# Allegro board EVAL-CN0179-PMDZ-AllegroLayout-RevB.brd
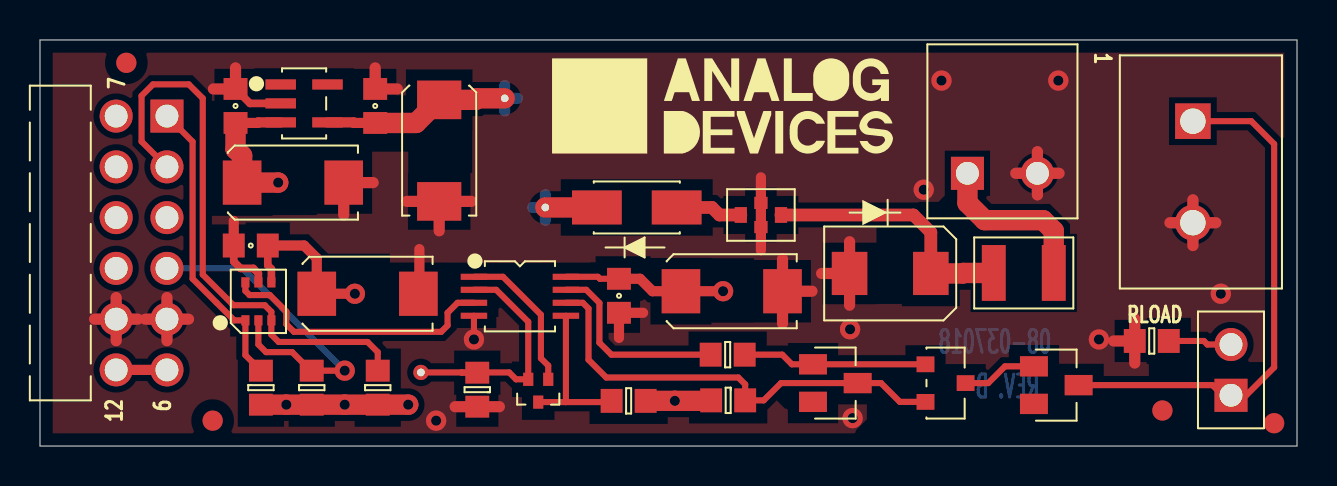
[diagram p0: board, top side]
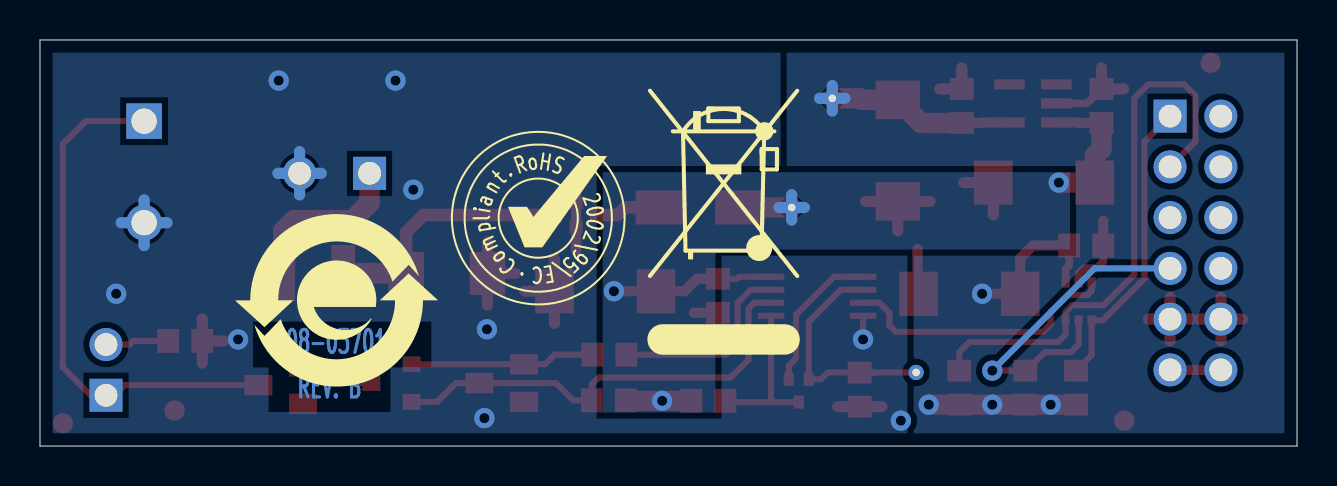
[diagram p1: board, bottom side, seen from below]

Outline 62.87 x 20.32 mm; copper layers: TOP, BOTTOM. Coordinates in mm from the lower left corner of the outline.
Outline path: 0,20.32 0,0 62.87,0 62.87,20.32 0,20.32

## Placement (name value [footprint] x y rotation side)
A1  AD8657ARMZ  [MSOP8]  24 7.49 270 top
C2  0.1uF  [C0805-4P]  36.05 11.56 180 top
C3  10uf  [C2312]  12.65 13.18 0 top
C4  0.1UF  [C0603]  9.78 17.02 270 top
C5  0.1UF  [C0603]  10.54 10.03 0 top
C6  10uf  [C2312]  16.38 7.62 0 top
C7  0.1UF  [C0603]  16.76 17.02 270 top
C8  10uf  [C2312]  19.96 14.78 270 top
C9  0.1UF  [C0603]  28.96 7.52 90 top
C10  10uf  [C2312]  34.59 7.75 0 top
CR1  SMBJ5357B-TP  [DO214AA3]  42.52 8.64 180 top
D1  SBR1A40SA-13  [SMA-2]  29.84 11.94 0 top
D2  BZX84C18LT1G  [SOT23]  39.78 3.15 270 top
F1  0.05A  [F1210_A]  49.2 8.66 180 top
I_OUT  OSTTC022162  [CNHDR1X2H406]  57.66 16.26 270 top
J1  M20-9990246  [CNHARWIN-M20-9990246]  59.56 2.54 90 top
NOREF  -  []  0 0 0 top
NOREF#2  -  []  26.16 50.97 0 top
NOREF#3  -  []  -219.71 -146.05 0 top
NOREF#4  -  []  -81.94 303.06 0 top
NOREF#5  -  []  34.16 17.02 0 top
NOREF#6  -  []  49.53 40.64 180 top
NOREF#7  -  []  -219.71 -146.05 0 top
NOREF#8  -  []  62.87 20.32 0 top
NOREF#9  -  [unnamed#2]  61.72 1.14 0 top
NOREF#10  -  [unnamed#2]  8.64 1.27 0 top
NOREF#11  -  []  6.35 16.51 0 top
NOREF#12  -  []  0 0 0 top
NOREF#13  -  []  0 0 0 top
NOREF#14  -  []  62.87 0 90 top
NOREF#15  -  []  153.85 303.38 0 top
NOREF#16  -  []  -219.71 -146.05 0 top
NOREF#17  -  []  49.53 0 90 top
NOREF#18  -  [unnamed#2]  4.32 19.18 0 top
NOREF#19  -  []  62.87 20.32 0 top
NOREF#20  -  []  2.54 40.64 270 top
NOREF#21  -  []  6.35 16.51 0 top
NOREF#22  -  [unnamed#2]  56.13 1.78 0 top
NOREF#23  -  []  2.54 0 0 top
NOREF#24  -  []  161.54 52.07 0 top
NOREF#25  -  []  19.41 21.46 180 bottom
NOREF#26  -  []  37.95 11.4 180 bottom
NOREF#27  -  []  48.03 7.29 180 bottom
P1  ED550/2DS  [CNOSTED550-2DS]  46.38 13.65 0 top
P2  TSW-106-25-F-D-RA  [CNHDRRA2X6H240]  6.35 16.51 270 top
Q1  2N7002T  [SOT523F]  24.92 2.77 180 top
Q2  SI2319DS-T1-E3  [SOT23-M3]  45.29 3.15 270 top
R1  10K  [R0603]  11.05 2.92 270 top
R2  10K  [R0603]  13.59 2.92 270 top
R3  10K  [R0603]  16.89 2.92 270 top
R4  1K  [R0603]  29.44 2.26 0 top
R5  2.49K  [R0603]  21.87 2.82 90 top
R6  100  [R0603]  34.39 4.57 0 top
R7  100  [R0603]  34.42 2.29 180 top
R8  250  [R0603]  55.6 5.26 0 top
U1  AD5641BKSZ  [SC70-6]  10.92 7.24 0 top
U2  ADR02BUJZ  [TSOT-5]  13.21 17.14 270 top
U3  BAS21LT1G  [SOT23]  50.83 3.05 270 top
UNK5V  TESTPAD  [TPC30D15]  23.24 17.4 0 top
V_RS  TESTPAD  [TPC30D15]  19.05 3.68 0 top
V_SY  TESTPAD  [TPC30D15]  25.27 11.94 0 top

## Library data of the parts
A1 = AD8657_V3: User Part Number: UPN; part number: AD8657_V3_SM-AD8657ARMZ,E019579,MSOP8,N/A
C2 = CAP4P_V3: Tolerance: -20+50; User Part Number: UPN; part number: CAP4P_V3_SM-0.1UF,25V,-20+50,E018137,C0805-4P; tolerance: -20+50
C3 C6 C8 C10 = CAPP: Tolerance: 10; User Part Number: UPN; part number: CAPP_SM-10UF,25V,10,E014558,C2312; tolerance: 10
C4 C5 C7 C9 = CAP: Tolerance: 10; User Part Number: UPN; alternate symbols: (C0402H22_ALT,C0201-2,C0402_A,C0402_ALT); part number: CAP_SM-0.1UF,25V,10,E007204,C0603; tolerance: 10
CR1 = DIOZNR: User Part Number: UPN; Tolerance: 5; part number: DIOZNR_SM-SMBJ5357B-TP,20V,5,E019629,DO214AA3; tolerance: 5
D1 = DIO: User Part Number: UPN; Tolerance: N/A; alternate symbols: (DO15_ALT); part number: DIO_SM-SBR1A40SA-13,40V,N/A,E015547,SMA-2; tolerance: N/A
D2 = DIOZNR3P_V3: User Part Number: UPN; Tolerance: 6; part number: DIOZNR3P_V3_SM-BZX84C18LT1G,18V,6,E019209,SOT23; tolerance: 6
F1 = FSFUSE: User Part Number: UPN; part number: FSFUSE_SM-0.05A,60V,E017159,F1210_A
I_OUT = CN2P: User Part Number: UPN; part number: CN2P_TH-OSTTC022162,E016936,CNHDR1X2H406
J1 = CN2P: User Part Number: UPN; part number: CN2P_TH-M20-9990246,E010843,CNHARWIN-M20-9990246
P1 = CN2P: User Part Number: UPN; part number: CN2P_TH-ED550/2DS,E019727,CNOSTED550-2DS
P2 = CN12P_V3: User Part Number: UPN; part number: CN12P_V3_TH-TSW-106-25-F-D-RA,E018495,CNHDRRA2X6H240
Q1 = TRAN2N7002: User Part Number: UPN; part number: TRAN2N7002_SM-2N7002T,E013674,SOT523F
Q2 = TRANSI2301DS: User Part Number: UPN; part number: TRANSI2301DS_SM-SI2319DS-T1-E3,E017810,SOT23-M3
R1-R3 = RES: Tolerance: 1; User Part Number: UPN; alternate symbols: (RRAD984L1500W75H520LD32;TO220H590_ALT;R0402_A;R0603_A); part number: RES_SM-10K,1/10W,1,E003671,R0603; tolerance: 1
R4 = RES: Tolerance: 0.1; User Part Number: UPN; alternate symbols: (RRAD984L1500W75H520LD32;TO220H590_ALT;R0402_A;R0603_A); part number: RES_SM-1K,1/10W,0.1,E003953,R0603; tolerance: 0.1
R5 = RES: Tolerance: 0.1; User Part Number: UPN; alternate symbols: (RRAD984L1500W75H520LD32;TO220H590_ALT;R0402_A;R0603_A); part number: RES_SM-2.49K,1/10W,0.1,E010318,R0603; tolerance: 0.1
R6 = RES: Tolerance: 1; User Part Number: UPN; alternate symbols: (RRAD984L1500W75H520LD32;TO220H590_ALT;R0402_A;R0603_A); part number: RES_SM-100,1/10W,1,E003668,R0603; tolerance: 1
R7 = RES: Tolerance: 0.1; User Part Number: UPN; alternate symbols: (RRAD984L1500W75H520LD32;TO220H590_ALT;R0402_A;R0603_A); part number: RES_SM-100,1/10W,0.1,E003963,R0603; tolerance: 0.1
R8 = RES: Tolerance: 0.05; User Part Number: UPN; alternate symbols: (RRAD984L1500W75H520LD32;TO220H590_ALT;R0402_A;R0603_A); part number: RES_SM-250,0.15W,0.05,E019192,R0603; tolerance: 0.05
U1 = AD56X1: User Part Number: UPN; part number: AD56X1_SM-AD5641BKSZ,E019530,SC70-6,N/A
U2 = ADR0X: User Part Number: UPN; part number: ADR0X_SM-ADR02BUJZ,E016933,TSOT-5,N/A
U3 = DIO3P_V2: User Part Number: UPN; Tolerance: N/A; part number: DIO3P_V2_SM-BAS21LT1G,250V,N/A,E019208,SOT23; tolerance: N/A
UNK5V V_RS V_SY = NCTESTPAD: User Part Number: UPN; part number: NCTESTPAD_TH-TESTPAD,E013464,TPC30D15

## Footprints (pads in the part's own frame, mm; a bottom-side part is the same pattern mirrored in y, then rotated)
C0603
  rect 1.092x1.194 smd: 1(-0.851,0) 2(0.851,0)
C0805-4P
  rect 0.61x0.787 smd: 1(-1.005,0) 3(1.005,0)
  rect 0.66x0.61 smd: G1(0,-0.605) G2(0,0.605)
C2312
  rect 1.93x2.21 smd: N(2.54,0) P(-2.54,0)
CNHARWIN-M20-9990246
  rect 1.651x1.651 hole 1.143: 1(0,0)
  round 1.651 hole 1.143: 2(2.54,0)
CNHDR1X2H406
  rect 1.778x1.778 hole 1.27: 1(0,0)
  round 1.778 hole 1.27: 2(5.08,0)
CNHDRRA2X6H240
  rect 1.651x1.651 hole 1.143: 1(0,0)
  round 1.651 hole 1.143: 2(2.54,0) 3(5.08,0) 4(7.62,0) 5(10.16,0) 6(12.7,0) 7(0,-2.54) 8(2.54,-2.54) 9(5.08,-2.54) 10(7.62,-2.54) 11(10.16,-2.54) 12(12.7,-2.54)
CNOSTED550-2DS
  rect 1.651x1.651 hole 1.143: 1(0,0)
  round 1.651 hole 1.143: 2(3.5,0)
DO214AA3
  rect 1.778x2.159 smd: A(2.032,0) C(-2.032,0)
F1210_A
  rect 1.194x2.794 smd: 1(-1.5,0) 2(1.5,0)
MSOP8
  rect 0.305x1.321 smd: 1(-0.975,-2.3) 2(-0.325,-2.3) 3(0.325,-2.3) 4(0.975,-2.3) 5(0.975,2.3) 6(0.325,2.3) 7(-0.325,2.3) 8(-0.975,2.3)
R0603
  rect 1.092x1.194 smd: 1(-0.851,0) 2(0.851,0)
SC70-6
  rect 0.406x0.508 smd: 1(-0.65,-0.95) 2(0,-0.95) 3(0.65,-0.95) 4(0.65,0.95) 5(0,0.95) 6(-0.65,0.95)
SMA-2
  rect 2.489x1.702 smd: A(1.995,0) C(-1.995,0)
SOT23
  rect 1.016x1.397 smd: 1(-0.94,-1.118) 2(0.94,-1.118) 3(0,1.118)
SOT23-M3
  rect 0.787x0.889 smd: 1(-0.94,-1.003) 2(0.94,-1.003) 3(0,1.003)
SOT523F
  rect 0.508x0.66 smd: 1(-0.5,-0.57) 2(0.5,-0.57) 3(0,0.57)
TPC30D15
  round 0.762 hole 0.381: 1(0,0)
TSOT-5
  rect 0.508x1.524 smd: 1(-0.95,-1.17) 2(0,-1.17) 3(0.95,-1.17) 4(0.95,1.17) 5(-0.95,1.17)
unnamed#2
  round 1.016 smd: (0,0)

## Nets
+5V: C5.2(N2) C6.P(N1) C7.2(N2) C8.P(N1) R1.2(N2) R2.2(N2) R3.2(N2) U1.4(VDD) U2.4(VOUT) UNK5V.1
AGND: A1.4(V-) C2.G1(GND1) C2.G2(GND2) C3.N(N2) C4.1(N1) C5.1(N1) C6.N(N2) C7.1(N1) C8.N(N2) C9.1(N1) C10.N(N2) CR1.A(P) I_OUT.2(N2) P1.2(N2) P2.5(GND1) P2.11(GND2) R5.1(N1) R8.1(N1) U1.5(GND) U2.2(GND)
+VSY: A1.8(V+) C3.P(N1) C4.2(N2) C9.2(N2) C10.P(N1) D1.C(N) R4.2(N2) R7.2(N2) U2.3(VIN) V_SY.1(N1)
DIN: P2.2(P2) R3.1(N1) U1.3(SDIN)
SCLK: P2.4(P4) R2.1(N1) U1.2(SCLK)
SYNC_N: P2.1(P1) R1.1(N1) U1.1(SYNC_N)
UNNAMED_7_AD56X1_I2_VOUT: A1.3(+IN) U1.6(VOUT)
UNNAMED_7_AD8657V3_I55_: A1.5(+IN) Q1.3(D) R4.1(N1)
UNNAMED_7_AD8657V3_I55_OUT: A1.7(OUT) R6.1(N1)
UNNAMED_7_AD8657V3_I56_OUT: A1.1(OUT) Q1.1(G)
UNNAMED_7_CN2P_I16_N1: I_OUT.1(N1) J1.1(N1) U3.3(C)
UNNAMED_7_CN2P_I53_N2: J1.2(N2) R8.2(N2)
UNNAMED_7_CN12PV3_I32_VCC1: P2.6(VCC1) P2.12(VCC2)
UNNAMED_7_DIO3PV2_I4_A: Q2.3(D) U3.1(A)
UNNAMED_7_DIOZNR3PV3_I3_N: A1.6(-IN) D2.3(N) Q2.2(S) R7.1(N1)
UNNAMED_7_DIOZNR3PV3_I3_P: D2.1(P) Q2.1(G) R6.2(N2)
UNNAMED_7_RES_I5_N2: A1.2(-IN) Q1.2(S) R5.2(N2) V_RS.1(N1)
UNNAMED_8_CAP4PV3_I22_IN: C2.1(IN) CR1.C(N) F1.2(N2)
UNNAMED_8_CAP4PV3_I22_OUT: C2.3(OUT) D1.A(P)
UNNAMED_8_CN2P_I18_N1: F1.1(N1) P1.1(N1)

Pads without a net: D2 2; P2 3 7 8 9 10; U2 1 5; U3 2

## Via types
v1: diameter 1.016, hole 0.508, TOP to BOTTOM, 17 vias

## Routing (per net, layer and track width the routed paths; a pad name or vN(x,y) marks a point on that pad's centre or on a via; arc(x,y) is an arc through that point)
+5V: length 27.6
  TOP w0.381: C5.2 11.39,9.04 11.57,8.86 U1.4
  TOP w0.508: C5.2 13.21,10.03 13.84,9.4 C6.P v1(15.75,7.62) ; U2.4 15.68,16.2 15.71,16.17 C7.2
  TOP w1.016: v1(18.41,2.07) R3.2 v1(15.24,2.07) R2.2 v1(12.32,2.07) R1.2 ; UNK5V.1 21.86,17.4 21.78,17.32 C8.P 18.81,16.17 C7.2
  BOTTOM w0.559: 22.61,17.4 UNK5V.1 ; UNK5V.1 23.88,17.4 ; UNK5V.1 23.24,16.76 ; UNK5V.1 23.24,18.03
AGND: length 69.4
  TOP w0.305: A1.4 v1(21.7,5.33)
  TOP w0.381: C5.1 9.69,9.23 10.03,8.89 10.67,8.89 10.92,8.64 U1.5 ; C4.1 10.5,17.14 U2.2
  TOP w0.508: 18.92,7.62 18.97,7.67 18.97,9.86 ; 36.05,13.45 C2.G1 C2.G2 36.05,9.79 ; 28.96,5.41 C9.1 30.16,6.67 ; C5.1 9.69,11.26
  TOP w0.559: I_OUT.2 57.66,12.32 ; I_OUT.2 56.51,11.18 ; I_OUT.2 58.8,11.18 ; I_OUT.2 57.66,10.03 ; 20.76,1.97 R5.1 22.97,1.97 ; C10.N 38.61,7.75 ; C10.N 37.13,9.36 ; C10.N 37.13,6.13 ; 19.96,10.77 C8.N ; C8.N 18.35,12.24 ; C8.N 21.58,12.24 ; 54.75,4.15 R8.1 ; R8.1 53.7,5.26 ; R8.1 54.75,6.36 ; P2.11 3.81,7.43 ; P2.11 3.81,5.27 ; P2.11 4.89,6.35 ; P2.11 2.73,6.35 ; 39.09,8.64 CR1.A ; CR1.A 40.49,10.22 ; CR1.A 40.49,7.05 ; 5.27,6.35 P2.5 ; P2.5 6.35,7.43 ; P2.5 7.43,6.35 ; P2.5 6.35,5.27 ; P1.2 50.96,13.65 ; P1.2 49.88,14.73 ; P1.2 49.88,12.57 ; P1.2 48.8,13.65 ; 16.66,13.18 C3.N 15.19,11.57 ; 9.78,18.92 C4.1 8.67,17.87 ; 16.76,18.92 C7.1 17.87,17.87
  BOTTOM w0.559: 56.51,11.18 I_OUT.2 ; I_OUT.2 57.66,12.32 ; I_OUT.2 57.66,10.03 ; I_OUT.2 58.8,11.18 ; P1.2 50.96,13.65 ; P1.2 48.8,13.65 ; P1.2 49.88,14.73 ; P1.2 49.88,12.57
  vias: v1(19.81,1.27) v1(40.51,5.84) v1(40.64,1.4) v1(44.2,12.83) v1(45.09,18.29) v1(50.93,18.29) v1(52.96,5.33) v1(59.05,7.62)
+VSY: length 23.8
  TOP w0.305: A1.8 27.9,8.47 28,8.37 C9.2
  TOP w0.508: v1(34.16,7.75) C10.P 30.63,7.75 30.01,8.37 C9.2 ; U2.3 10.92,16.2 10.89,16.17 C4.2
  TOP w1.016: v1(11.91,13.18) C3.P 10.11,14.53 9.78,14.86 C4.2 ; D1.C V_SY.1 ; R4.2 v1(31.75,2.26) 33.54,2.26 R7.2
  BOTTOM w0.559: 25.27,11.3 V_SY.1 ; V_SY.1 24.64,11.94 ; V_SY.1 25.91,11.94 ; V_SY.1 25.27,12.57
DIN: length 28.4
  TOP w0.305: P2.2 5.08,15.24 5.08,17.53 5.65,18.1 7.44,18.1 8.14,17.4 8.14,8.58 9.67,7.05 11.24,7.05 11.57,6.72 U1.3 11.57,5.57 11.94,5.21 16.38,5.21 16.89,4.7 R3.1
SCLK: length 17.1
  TOP w0.305: v1(15.24,3.77) R2.1 13.54,3.77 12.61,4.7 11.3,4.7 10.92,5.08 U1.2
  BOTTOM w0.305: v1(15.24,3.77) 10.12,8.89 P2.4
SYNC_N: length 15
  TOP w0.305: R1.1 10.27,4.55 U1.1 9.71,6.29 8.83,7.18 7.63,8.37 7.63,15.23 P2.1
UNNAMED_7_AD56X1_I2_VOUT: length 14.1
  TOP w0.305: A1.3 20.88,7.17 20.38,6.67 20.38,6.03 20.07,5.71 12.7,5.71 12.32,6.1 12.32,6.73 11.5,7.55 10.48,7.55 10.27,7.76 U1.6
UNNAMED_7_AD8657V3_I55_: length 8
  TOP w0.305: A1.5 26.3,2.21 26.29,2.2 ; 26.29,2.2 Q1.3 ; 26.29,2.2 28.53,2.2 R4.1
UNNAMED_7_AD8657V3_I55_OUT: length 9.7
  TOP w0.305: A1.7 27.32,7.82 27.98,7.16 27.98,5.17 28.57,4.57 R6.1
UNNAMED_7_AD8657V3_I56_OUT: length 7.5
  TOP w0.305: A1.1 23.15,8.47 25.05,6.57 25.05,4.39 25.42,4.02 Q1.1
UNNAMED_7_CN2P_I16_N1: length 26.3
  TOP w0.305: I_OUT.1 60.58,16.26 61.72,15.11 61.72,3.94 60.33,2.54 J1.1 59.14,2.54 58.64,3.05 51.94,3.05
UNNAMED_7_CN2P_I53_N2: length 3.2
  TOP w0.305: R8.2 58.2,5.26 58.38,5.08 J1.2
UNNAMED_7_CN12PV3_I32_VCC1: length 2.5
  TOP w0.508: P2.12 P2.6
UNNAMED_7_DIO3PV2_I4_A: length 3.8
  TOP w0.305: Q2.3 47.42,3.15 48.26,3.99 U3.1
UNNAMED_7_DIOZNR3PV3_I3_N: length 22.7
  TOP w0.305: A1.6 27.15,7.17 27.43,6.88 27.43,4.32 28.32,3.43 34.92,3.43 35.27,3.09 R7.1 36.2,2.29 37.06,3.15 D2.3 42.06,3.15 43,2.21 Q2.2
UNNAMED_7_DIOZNR3PV3_I3_P: length 9.2
  TOP w0.305: Q2.1 D2.1 37.6,4.09 37.12,4.57 R6.2
UNNAMED_7_RES_I5_N2: length 12.6
  TOP w0.305: 21.08,3.68 21.09,3.67 R5.2 ; 21.08,3.68 V_RS.1 ; 21.08,3.68 23.46,3.68 23.81,3.34 Q1.2 24.42,6.22 22.81,7.82 A1.2
UNNAMED_8_CAP4PV3_I22_IN: length 13.1
  TOP w0.635: CR1.C 44.55,10.69 43.68,11.56 C2.1
  TOP w1.016: CR1.C 46.15,8.64 46.18,8.66 F1.2
UNNAMED_8_CAP4PV3_I22_OUT: length 3.4
  TOP w0.635: D1.A 33.6,11.94 33.98,11.56 C2.3
UNNAMED_8_CN2P_I18_N1: length 8.5
  TOP w1.016: F1.1 50.7,10.77 50.16,11.3 47.24,11.3 46.38,12.16 P1.1

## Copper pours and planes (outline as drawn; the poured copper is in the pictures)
+5V on BOTTOM: 0.63,0.63 0.63,19.69 25.52,19.69 25.52,14.01 11.05,14.01 11.05,9.52 19.18,9.52 19.18,0.63
AGND on TOP: 0.64,0.64 0.64,19.68 62.23,19.68 62.23,0.64 ; 22 cut-outs
AGND on BOTTOM: 0.64,0.64 0.64,19.68 62.23,19.68 62.23,0.64
+VSY on BOTTOM: 11.35,13.7 34.72,13.7 34.72,1.68 29.09,1.68 29.09,9.83 11.35,9.83

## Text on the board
BOTTOM: 08-037018 | REV. B
Ref Des/Silkscreen Top: RLOAD
PAGE_OUTLINE: B | AS PER ECR-044611 | 26DEC13 | G.ARINUEL
User.15: ROHS COMPLIANCE NOTE: | THE EU RoHS DIRECTIVE 2002/95/EC | HOMOGENOUS MATERIALS IN THIS BOARD SHALL BE COMPLIANT | 100 MICRO INCHES NICKEL/ | 2-8 MICRO INCHES GOLD
User.45: EVAL-CN0179-PMDZ REV.B | +18V | GND | FIGURE | SIZE | 15.0 | 20.0 | 45.0 | 50.0 | DRILL CHART: TOP to BOTTOM | ALL UNITS ARE IN MILS | TOLERANCE | +3.0/-3.0 | PLATED | QTY | 3 | 17 | 16 | 2
